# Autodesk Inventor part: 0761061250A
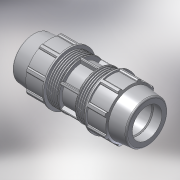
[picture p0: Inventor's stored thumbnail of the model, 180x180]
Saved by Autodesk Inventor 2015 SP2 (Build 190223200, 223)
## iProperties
Created: 2017-02
Part Number: 0761061250A
Material: PVC-Piping
Description: PLASSON REPAIR COUPLER 125
Document SubType Name: Modeling
Designer: KIM
Mass: 2387.75 g
Surface Area: 2478.17 cm^2
Volume: 1705.54 cm^3
Density: 1.4 g/cm^3
Appearance: Smooth - White
Author: KIM
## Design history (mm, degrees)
derived "87610.ipt"
feature "Solid1::87610.ipt"
tag "TaggingFeature1"
body "Solid1"
other parameters: "d2" = 125, "d4" = 38.33333, "d5" = 65.71429, "d7" = 212, "d8" = 159, "d9" = 65.71429, "d11" = 6.57143, "d12" = 169.6, "d13" = 120 deg, "d14" = 162.5, "d15" = 6 deg, "d16" = 190.8, "d18" = 6.25, "d19" = 35 deg, "d20" = 17.5 deg, "d21" = 197.16, "d23" = 0, "d25" = 360 deg, "d27" = 4.24, "d33" = 2.5, "d34" = 10.6, "d36" = 0, "d37" = 2.5, "d38" = 2.5, "d40" = 360 deg, "d42" = 82.8, "d46" = 3.75, "d50" = 5.75, "d51" = 0, "d53" = 4.20571, "d54" = 4.20571, "d57" = 8.41143, "d62" = 186.984, "d_" = 125, "E_" = 212, "l_" = 143, "d52" = 42.05714
